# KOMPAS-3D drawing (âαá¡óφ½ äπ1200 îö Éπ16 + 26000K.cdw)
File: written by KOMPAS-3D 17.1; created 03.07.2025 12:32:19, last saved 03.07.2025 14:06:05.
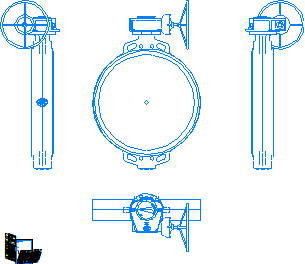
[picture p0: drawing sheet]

Sheet 1: A4, portrait

Title block, sheet 1: sheets: 1; sheet format: A4; stored path: \\adlc.lan\data\АДЛ_ПКД\3D-модели\ADL production\Дисковые поворотные затворы ГРАНВЭЛ\межфланцевый с китайским редуктором Ру16\KOMPAS 2D\Гранвэл Ду1200 МФ Ру16 + 26000K.cdw

Views: Проекционный вид 2, Проекционный вид 3
Referenced files in \\adlc.lan\data\АДЛ_ПКД\3D-модели\ADL production\Дисковые поворотные затворы ГРАНВЭЛ\межфланцевый с китайским редуктором Ру16\KOMPAS 3D\: Гранвэл Ду1200 МФ Ру16 + 26000K.m3d
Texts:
  Andrey
  АДЛ
Dimensions and other numbers on the sheet: 1:1; 1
